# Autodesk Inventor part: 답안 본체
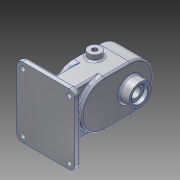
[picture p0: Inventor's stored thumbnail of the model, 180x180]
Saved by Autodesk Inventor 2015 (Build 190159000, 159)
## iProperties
Created: 2020-09
Part Number: 답안 본체
Material: 알루미늄 6061
Document SubType Name: Modeling
Designer: 1015698
Mass: 1440.44 g
Surface Area: 785.392 cm^2
Volume: 533.497 cm^3
Density: 2.7 g/cm^3
Appearance: 알루미늄 - 평지
Author: 1015698
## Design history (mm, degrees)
sketch "스케치1"
  geometry: L1 (50, -60)-(-50, -60); L2 (-50, -60)-(-50, 60); L3 (-50, 60)-(50, 60); L4 (50, 60)-(50, -60); L5 (50, -60)-(-50, 60); L6 (-50, -60)-(50, 60); 1 further point
  constraints: 12 end point, 2 midpoint, 2 parallel, 1 horizontal, 1 perpendicular
  dimensions: "d0" = 100 distance between parallel lines of L2 L4; "d1" = 120 distance between parallel lines of L3 L1
extrude "돌출1" new body sketch "스케치1" distance "d2" = 10; taper "d3" = 0 deg
node "작업 평면5"
  node "작업 평면4"
sketch "스케치2"
  geometry: L1 (112, 0)-(68, 0); L2 (112, 40)-(68, 40); L3 (68, -40)-(112, -40); L4 (0, 60)-(0, -60) reference; A1 r 40 centre (112, 0) between (112, -40) and (112, 40); A2 r 40 centre (68, 0) between (68, 40) and (68, -40); 3 further points
  constraints: 8 end point, 4 point on circle, 4 tangent, 2 centre point, 2 midpoint, 1 horizontal, 1 horizontal alignment, 1 parallel
  dimensions: "d8" = 90 distance from line of L4 point (90, 0); "d9" = 40 radius of A1; "d10" = 44 distance of L1.end L1.start
extrude "돌출2" join sketch "스케치2" distance "d11" = 53; taper "d12" = 0 deg
sketch "스케치3"
  geometry: L1 (40, 112)-(40, 68) reference; L2 (-40, 68)-(-40, 112) reference; L3 (24, 112)-(24, 68); L4 (-24, 68)-(-24, 112); A1 r 40 centre (0, 112) between (40, 112) and (-40, 112) reference; A2 r 40 centre (0, 68) between (-40, 68) and (40, 68) reference; A3 r 24 centre (0, 112) between (24, 112) and (-24, 112); A4 r 24 centre (0, 68) between (-24, 68) and (24, 68); 1 further point
  constraints: 4 end point, 4 point on circle, 2 centre point, 3 other
  dimensions: "d13" = 24 radius of A3
extrude "돌출3" cut sketch "스케치3" distance "d14" = 29; taper "d15" = 0 deg
sketch "스케치4"
  geometry: C1 r 12.5 at (0, 112); C2 r 12.5 at (0, 68); A1 r 24 centre (0, 112) between (24, 112) and (-24, 112) reference; A2 r 24 centre (0, 68) between (-24, 68) and (24, 68) reference; 1 further point
  constraints: 2 centre point, 2 coincident
  dimensions: "d16" = 25 diameter of C1; "d17" = 25 diameter of C2
extrude "돌출4" cut sketch "스케치4" distance "d18" = 15; taper "d19" = 0 deg
sketch "스케치5"
  geometry: C1 r 19 at (0, 112); A1 r 40 centre (0, 112) between (40, 112) and (-40, 112) reference; 1 further point
  constraints: 1 centre point, 1 coincident
  dimensions: "d20" = 38 diameter of C1
extrude "돌출5" join sketch "스케치5" distance "d21" = 17; taper "d22" = 0 deg
hole "구멍1" diameter "d25" = 17; stored, may be unused: countersink angle "d29" = 90 deg, drill point angle "d31" = 118 deg; dims "d23" = 10, "d24" = 10, "d26" = 6, "d27" = 28, "d28" = 7.3, "d30" = 8
sketch "스케치6"
  geometry: L1 (0, 44)-(0, 0) reference; C1 r 11 at (14, 22); 3 further points
  constraints: 1 centre point, 1 horizontal alignment, 1 midpoint
  dimensions: "d33" = 14 distance of C1.centre point (0, 22); "d34" = 22 diameter of C1
extrude "돌출6" join sketch "스케치6" distance "d35" = 10; taper "d36" = 0 deg
hole "구멍2" diameter "d39" = 8.376; stored, may be unused: countersink angle "d43" = 90 deg, drill point angle "d45" = 0 deg; dims "d40" = 35, "d41" = 28, "d42" = 7.3, "d44" = 42.3, "d112" = 10, "d113" = 10
sketch "스케치7"
  geometry: L1 (-24, 68)-(-24, 112) reference; L2 (24, 112)-(24, 68) reference; L3 (-31, 112)-(-31, 68); L4 (31, 68)-(31, 112); A1 r 24 centre (0, 112) between (24, 112) and (-24, 112) reference; A2 r 24 centre (0, 68) between (-24, 68) and (24, 68) reference; A3 r 31 centre (0, 68) between (-31, 68) and (31, 68); A4 r 31 centre (0, 112) between (31, 112) and (-31, 112); 7 further points
  constraints: 6 point on circle, 4 coincident, 4 end point, 2 centre point, 3 other
  dimensions: "d47" = 31 radius of A4
hole "구멍3" sketch "스케치7" at (0, 143), (-31, 112), (31, 112), (31, 68), (-31, 68), (0, 37) diameter "d48" = 4.134; stored, may be unused: countersink angle "d52" = 90 deg, drill point angle "d54" = 118 deg; dims "d49" = 10, "d50" = 28, "d51" = 7.3, "d53" = 12
sketch "스케치8"
  geometry: L1 (-50, 60)-(-50, -60) reference; L2 (-50, -60)-(50, -60) reference; L3 (50, -60)-(50, 60) reference; L4 (-50, 60)-(50, 60) reference; L5 (25, 40)-(25, -40); L6 (-12, 40)-(-12, -40); L7 (-50, 40)-(50, 40); L8 (-50, -40)-(50, -40); 1 further point
  constraints: 8 end point, 6 point on line, 3 perpendicular, 1 parallel
  dimensions: "d55" = 25 distance between parallel lines of L3 L5; "d56" = 37 distance between parallel lines of L5 L6; "d57" = 40 distance from line of L7 point (0, 0); "d58" = 80 distance between parallel lines of L8 L7
extrude "돌출7" join sketch "스케치8" stored distance "d59" = 10; taper "d60" = 0 deg
fillet "모깎기1" dims "d61" = 10
hole "구멍4" diameter "d64" = 9; stored, may be unused: countersink angle "d68" = 90 deg, drill point angle "d70" = 118 deg; dims "d62" = 10, "d63" = 10, "d65" = 10, "d66" = 28, "d67" = 7.3, "d69" = 12
hole "구멍5" diameter "d73" = 9; stored, may be unused: countersink angle "d77" = 90 deg, drill point angle "d79" = 118 deg; dims "d71" = 10, "d72" = 10, "d74" = 10, "d75" = 28, "d76" = 7.3, "d78" = 12
hole "구멍6" diameter "d82" = 9; stored, may be unused: countersink angle "d86" = 90 deg, drill point angle "d88" = 118 deg; dims "d80" = 10, "d81" = 10, "d83" = 10, "d84" = 28, "d85" = 7.3, "d87" = 12
hole "구멍7" diameter "d91" = 9; stored, may be unused: countersink angle "d95" = 90 deg, drill point angle "d97" = 118 deg; dims "d89" = 10, "d90" = 10, "d92" = 10, "d93" = 28, "d94" = 7.3, "d96" = 12
chamfer "모따기1" distance "d98" = 0.7; stored, may be unused: second distance "d99" = 2, angle "d100" = 30 deg
fillet "모깎기2" dims "d101" = 0.5
chamfer "모따기2" distance "d102" = 1; stored, may be unused: second distance "d103" = 2, angle "d104" = 45 deg
fillet "모깎기3" dims "d105" = 3
sketch "스케치9"
  geometry: L1 (-40, 57)-(40, 57) reference; L2 (-47, -50)-(-47, 50) reference; 2 further points
  constraints: 1 other
  dimensions: "d106" = 60 distance from line of point (-35, -3) L1; "d107" = 12 distance from line of L2 point (-35, -3)
extrude "돌출8" join sketch "스케치9" distance "d108" = 0.5; taper "d109" = 0 deg
hole "구멍8" diameter "d114" = 8.376; stored, may be unused: countersink angle "d118" = 90 deg, drill point angle "d120" = 0 deg; dims "d115" = 30, "d116" = 28, "d117" = 7.3, "d119" = 37.3, "d121" = 10, "d122" = 10
node "솔리드1"
mirror "대칭1"
